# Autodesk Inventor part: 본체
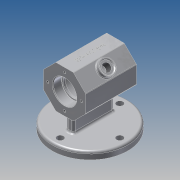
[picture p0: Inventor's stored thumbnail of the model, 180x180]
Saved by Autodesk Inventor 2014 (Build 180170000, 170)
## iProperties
Created: 2021-02
Part Number: 본체
Material: 알루미늄 6061
Document SubType Name: Modeling
Designer: kb542
Density: 2.71 g/cm^3
Appearance: 알루미늄 - 평지
Mass: 558.806 g
Surface Area: 509.67 cm^2
Volume: 206.202 cm^3
Author: kb542
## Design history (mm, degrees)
sketch "스케치1" dims "d0" = 58
  geometry: L1 (12.012, 29)-(29, 12.012); L2 (29, 12.012)-(29, -12.012); L3 (29, -12.012)-(12.012, -29); L4 (12.012, -29)-(-12.012, -29); L5 (-12.012, -29)-(-29, -12.012); L6 (-29, -12.012)-(-29, 12.012); L7 (-29, 12.012)-(-12.012, 29); L8 (-12.012, 29)-(12.012, 29); 4 further points
  constraints: 16 end point, 2 coincident, 2 vertical alignment, 1 midpoint, 19 other
extrude "돌출1" new body sketch "스케치1" stored distance "d1" = 70; taper "d2" = 0 deg
sketch "스케치2"
  geometry: L1 (0, 35)-(0, -35); L2 (0, 35)-(16, 35); L3 (16, 35)-(16, 23.3); L4 (15.7, 23)-(14, 23); L5 (14, 23)-(14, 20); L6 (14, 20)-(19, 20); L7 (22, 17)-(22, -17); L8 (19, -20)-(14, -20); L9 (14, -20)-(14, -23); L10 (14, -23)-(15.7, -23); L11 (16, -23.3)-(16, -35); L12 (16, -35)-(0, -35); A1 r 0.3 centre (15.7, 23.3) between (15.7, 23) and (16, 23.3); A2 r 0.3 centre (15.7, -23.3) between (16, -23.3) and (15.7, -23); A3 r 3 centre (19, -17) between (19, -20) and (22, -17); A4 r 3 centre (19, 17) between (22, 17) and (19, 20); 3 further points
  constraints: 24 end point, 8 point on circle, 8 tangent, 5 perpendicular, 4 centre point, 4 horizontal, 2 equal radius, 2 midpoint, 2 parallel, 1 coincident, 1 horizontal alignment, 1 vertical
  dimensions: "d3" = 32 diameter of L3 L1; "d4" = 28 diameter of L5 L1; "d5" = 32 diameter of L11 L1; "d7" = 28 diameter of L9 L1; "d8" = 44 diameter of L7 L1; "d9" = 70 distance between parallel lines of L12 L2; "d10" = 12 distance between parallel lines of L2 L4; "d11" = 12 distance between parallel lines of L12 L10; "d12" = 40 distance between parallel lines of L8 L6; "d13" = 3 distance of L4.end L5.end (derived); "d14" = 0.3 radius of A1; "d15" = 3 radius of A3
revolve "회전1" sketch "스케치2" stored, may be unused: angle "d16" = 90 deg
sketch "스케치3" dims "d17" = 46
  geometry: C1 r 16 at (0, 0) reference; 2 further points
  constraints: 2 vertical alignment, 1 coincident, 2 other
hole "구멍1" sketch "스케치3" at (0, 23) diameter "d18" = 3.242; stored, may be unused: countersink angle "d22" = 90 deg, drill point angle "d24" = 118 deg; dims "d19" = 8, "d20" = 4, "d21" = 2, "d23" = 10
sketch "스케치4"
  geometry: L1 (-24.024, 70)-(0, 70) reference; L2 (16.988, 70)-(16.988, 0) reference; C1 r 10 at (-12.012, 35); 1 further point
  constraints: 1 centre point, 1 coincident
  dimensions: "d28" = 20 diameter of C1; "d29" = 29 distance from line of L2 point (-12.012, 35) (derived); "d30" = 35 distance from line of L1 point (-12.012, 35) (derived)
extrude "돌출2" join sketch "스케치4" distance "d31" = 5; taper "d32" = 0 deg
fillet "모깎기1" dims "d33" = 1
sketch "스케치5"
  geometry: C1 r 10 at (0, 0) reference; C2 r 8 at (0, 0)
  constraints: 1 centre point, 1 coincident
  dimensions: "d34" = 16 diameter of C2
extrude "돌출3" cut sketch "스케치5" distance "d35" = 2; taper "d36" = 0 deg
hole "구멍2" diameter "d39" = 10.917; stored, may be unused: countersink angle "d43" = 90 deg, drill point angle "d45" = 118 deg; dims "d37" = 10, "d38" = 10, "d40" = 8, "d41" = 4, "d42" = 2, "d44" = 10
sketch "스케치6"
  geometry: L1 (23.196, 0)-(0, 0) reference; L2 (-17.402, 70)-(-17.402, 0) reference; 2 further points
  constraints: 1 coincident, 1 other
  dimensions: "d46" = 29 distance from line of point (11.598, 35) L2 (derived); "d47" = 35 distance from line of L1 point (11.598, 35) (derived)
feature "엠보싱1" sketch "스케치6" dims "d0" = 58, "d3" = 32, "d4" = 28, "d5" = 32, "d7" = 28, "d8" = 44, "d9" = 70, "d10" = 12, "d11" = 12, "d12" = 40, "d13" = 3 (derived), "d14" = 0.3, "d15" = 3, "d48" = 0.5, "d49" = 0
node "작업 평면1"
sketch "스케치7" dims "d52" = 82
  geometry: C1 r 52 at (0, 0); C2 r 4.5 at (0, 41); C3 r 4.5 at (-41, 0); C4 r 4.5 at (0, -41); C5 r 4.5 at (41, 0); 2 further points
  constraints: 5 centre point, 2 coincident, 2 vertical alignment, 11 other
  dimensions: "d51" = 104 diameter of C1; "d53" = 9 diameter of C2; "d56" = 360 deg dimension on point (0, 0) C2.centre (derived)
extrude "돌출4" join sketch "스케치7" distance "d58" = 10; taper "d59" = 0 deg
fillet "모깎기2" dims "d60" = 3
sketch "스케치8"
  geometry: L1 (-5, 28)-(5, 28); L2 (5, 28)-(5, -28); L3 (5, -28)-(-5, -28); L4 (-5, -28)-(-5, 28); C1 r 49 at (0, 0) reference; 3 further points
  constraints: 8 end point, 3 midpoint, 2 parallel, 2 vertical alignment, 1 horizontal, 1 horizontal alignment, 1 perpendicular
  dimensions: "d61" = 10 distance between parallel lines of L2 L4; "d62" = 56 distance between parallel lines of L3 L1
extrude "돌출5" join sketch "스케치8" stored distance "d63" = 10; taper "d64" = 0 deg
chamfer "모따기1" distance "d65" = 1; stored, may be unused: second distance "d66" = 2, angle "d67" = 45 deg
fillet "모깎기3" dims "d68" = 3
fillet "모깎기4" dims "d69" = 3
node "솔리드1"
pattern_circular "원형 패턴1" dims angle "d26" = 360 deg
mirror "대칭1"
other parameters: "d50" = -62
